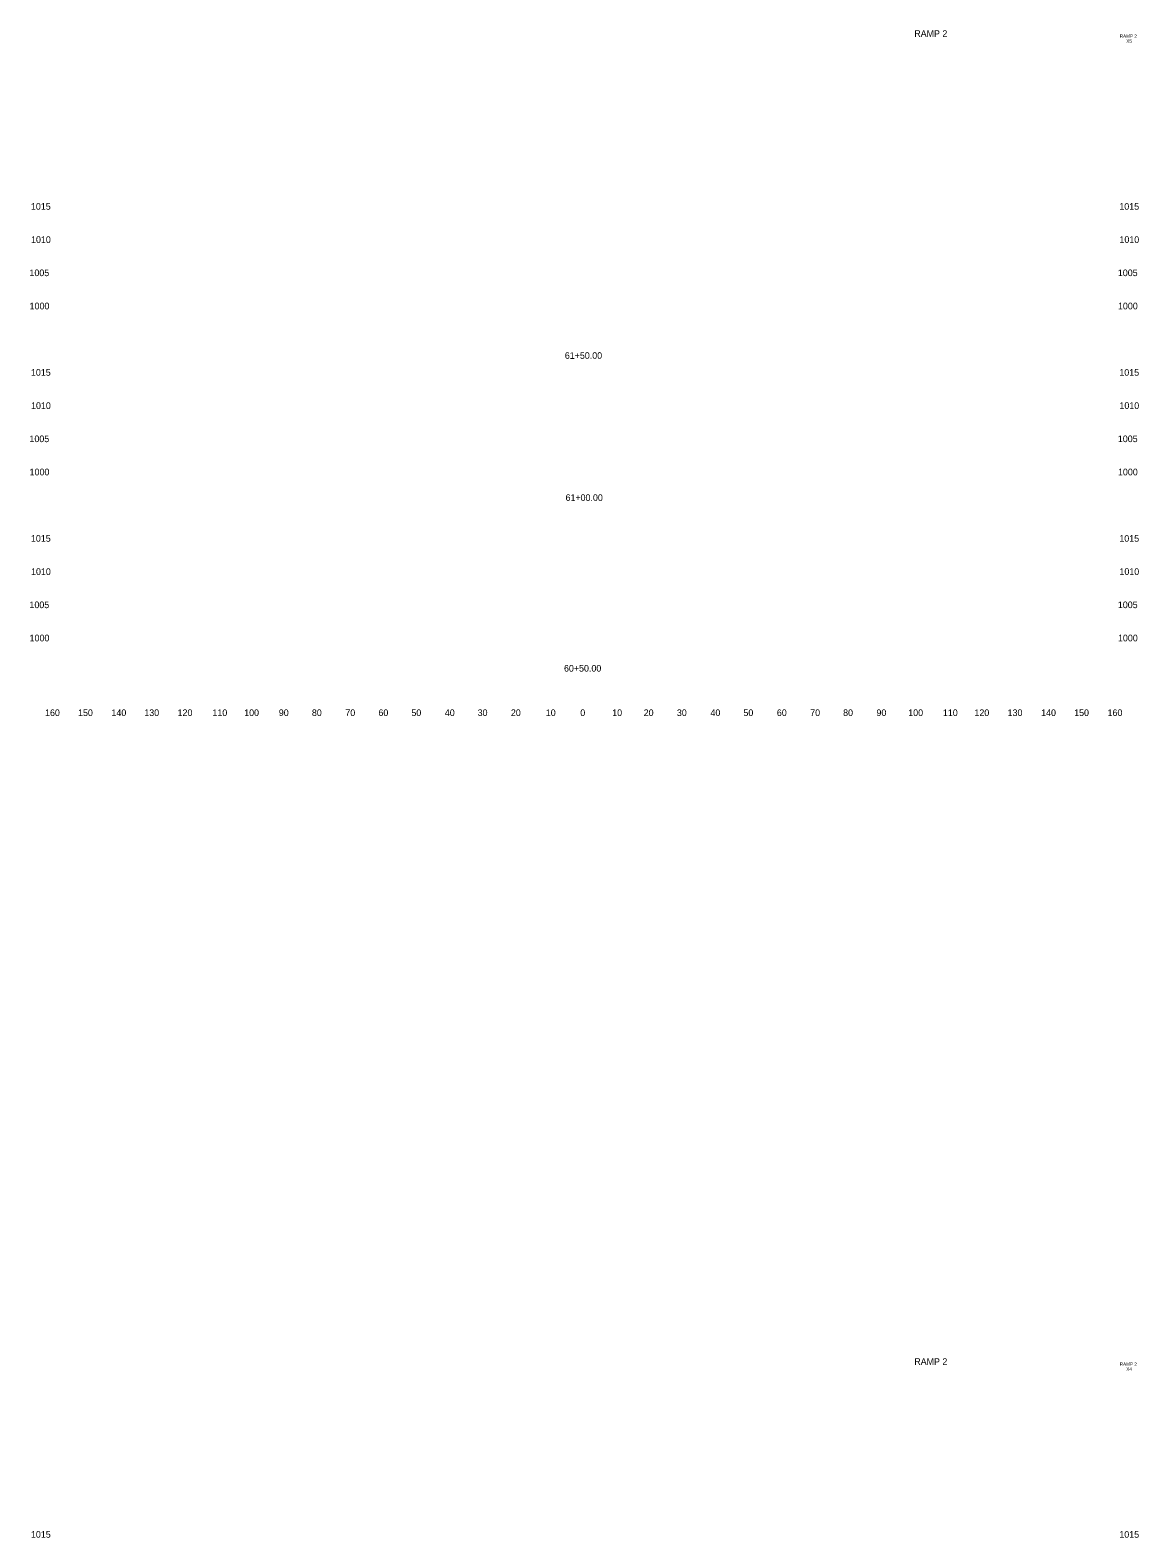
# Model space of a CAD drawing. Extents: x 4994 to 5328, y 4997 to 8804.
# Drawn here: x 4993.6 to 5327.5, y 6350 to 6804.1 of the extents above; entities that cross this region are included whole.
import ezdxf

# ---------------------------------------------------------------- set-up
doc = ezdxf.new("R2010")
doc.units = 0
for name, color, linetype in [('RD_SHT_ID', 7, 'Continuous'), ('RD_XS_TX_Offset', 7, 'Continuous'), ('RD_XS_TX_Station', 7, 'Continuous')]:
    doc.layers.add(name, color=color, linetype=linetype)

msp = doc.modelspace()

# ---------------------------------------------------------------- texts
at = {"layer": 'RD_SHT_ID'}
for s, height, p in [('RAMP 2', 2, (5259.89, 6802.06)), ('RAMP 2', 1, (5321.78, 6801.8)), ('X5', 1, (5323.74, 6800.3)), ('RAMP 2', 2, (5259.89, 6402.06)), ('RAMP 2', 1, (5321.78, 6401.8)), ('X4', 1, (5323.74, 6400.3))]:
    msp.add_text(s, height=height, dxfattribs=at).set_placement(p)
at = {"layer": 'RD_XS_TX_Offset'}
for s, p in [('1015', (4993.85, 6750)), ('1015', (5321.65, 6750)), ('1010', (4993.88, 6740)), ('1010', (5321.68, 6740)), ('1005', (4993.4, 6730)), ('1005', (5321.2, 6730)), ('1000', (4993.44, 6720)), ('1000', (5321.24, 6720)), ('1015', (4993.85, 6700)), ('1015', (5321.65, 6700)), ('1010', (4993.88, 6690)), ('1010', (5321.68, 6690)), ('1005', (4993.4, 6680)), ('1005', (5321.2, 6680)), ('1000', (4993.44, 6670)), ('1000', (5321.24, 6670)), ('1015', (4993.85, 6650)), ('1015', (5321.65, 6650)), ('1010', (4993.88, 6640)), ('1010', (5321.68, 6640)), ('1005', (4993.4, 6630)), ('1005', (5321.2, 6630)), ('1000', (4993.44, 6620)), ('1000', (5321.24, 6620)), ('160', (4998.1, 6597.5)), ('150', (5008.04, 6597.5)), ('140', (5018.1, 6597.5)), ('130', (5027.99, 6597.5)), ('120', (5038.01, 6597.5)), ('110', (5048.51, 6597.5)), ('100', (5058.07, 6597.5)), ('90', (5068.5, 6597.5)), ('80', (5078.46, 6597.5)), ('70', (5088.54, 6597.5)), ('60', (5098.5, 6597.5)), ('50', (5108.43, 6597.5)), ('40', (5118.5, 6597.5)), ('30', (5128.39, 6597.5)), ('20', (5138.4, 6597.5)), ('10', (5148.91, 6597.5)), ('0', (5159.3, 6597.5)), ('0', (5159.3, 6597.5)), ('10', (5168.91, 6597.5)), ('20', (5178.4, 6597.5)), ('30', (5188.39, 6597.5)), ('40', (5198.5, 6597.5)), ('50', (5208.43, 6597.5)), ('60', (5218.5, 6597.5)), ('70', (5228.54, 6597.5)), ('80', (5238.46, 6597.5)), ('90', (5248.5, 6597.5)), ('100', (5258.07, 6597.5)), ('110', (5268.51, 6597.5)), ('120', (5278.01, 6597.5)), ('130', (5287.99, 6597.5)), ('140', (5298.1, 6597.5)), ('150', (5308.04, 6597.5)), ('160', (5318.1, 6597.5)), ('1015', (4993.85, 6350)), ('1015', (5321.65, 6350))]:
    msp.add_text(s, height=2, dxfattribs=at).set_placement(p)
at = {"layer": 'RD_XS_TX_Station'}
for s, p in [('61+50.00', (5154.64, 6705.09)), ('61+00.00', (5154.86, 6662.29)), ('60+50.00', (5154.39, 6610.88))]:
    msp.add_text(s, height=2, dxfattribs=at).set_placement(p)

doc.saveas('drawing.dxf')
